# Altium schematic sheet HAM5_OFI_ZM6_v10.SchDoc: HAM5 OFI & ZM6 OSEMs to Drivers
size C; Engineer: L. Sanchez; Organization: LIGO Laboratory; Address1: California Institute of Technology; Address2: Massachusetts Institute of Technology; DocumentNumber: D1002740; Revision: v10; SheetNumber: 3; SheetTotal: 8
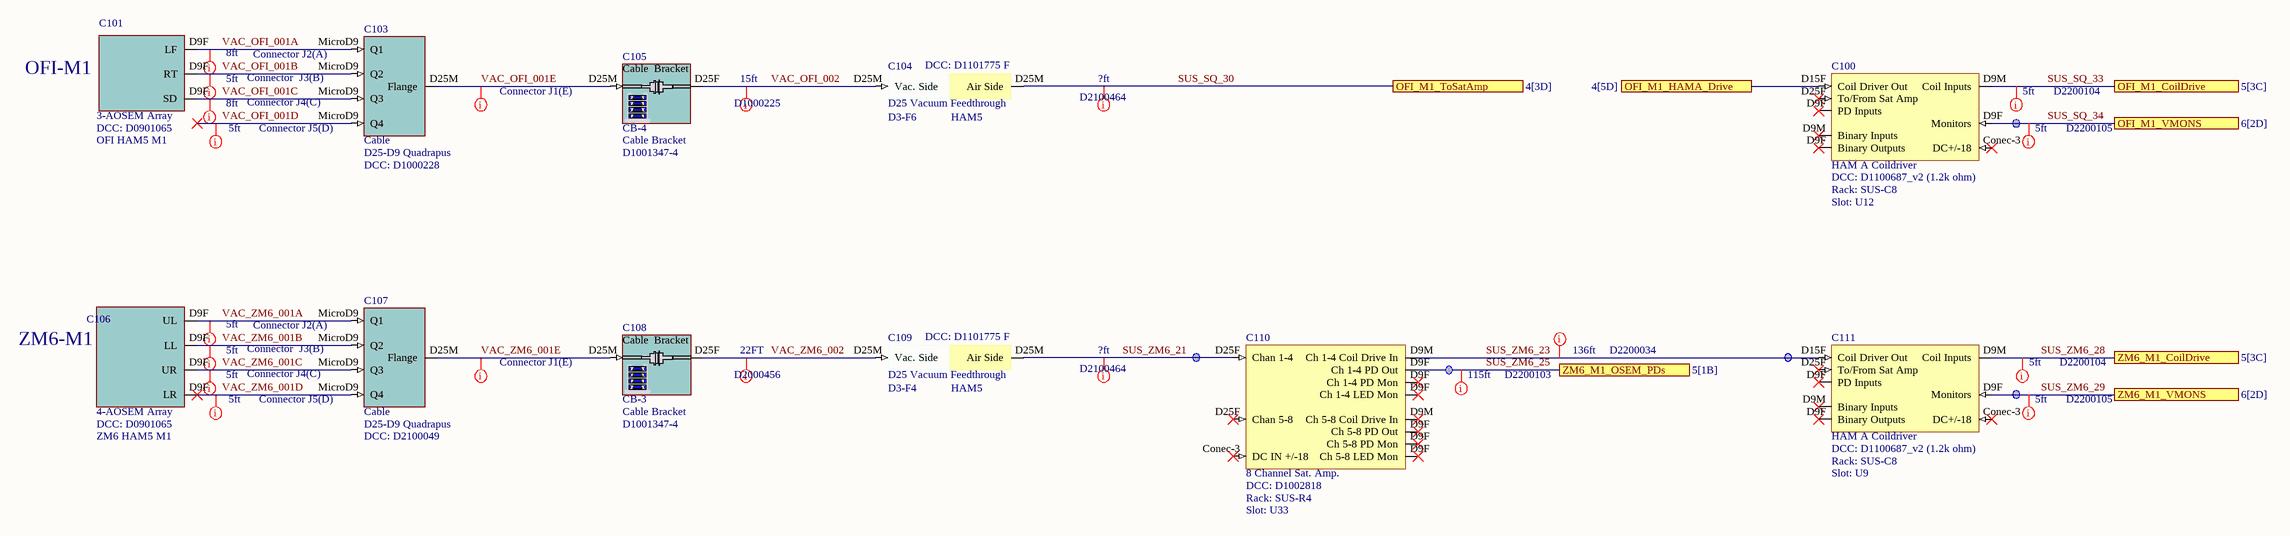
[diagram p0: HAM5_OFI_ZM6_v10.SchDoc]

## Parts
C100  HAM A Coildriver  DCC: D1100687_v2 (1.2k ohm)  Rack: SUS-C8  Slot: U12
C101  3-AOSEM Array  DCC: D0901065  Parameter: OFI HAM5 M1
C103  Cable  value D25-D9 Quadrapus  DCC: D1000228
C104  D25 Vacuum Feedthrough  DCC: D1101775 F  Feedthrough: D3-F6  Chamber: HAM5
C105  Slot: CB-4  DCC: D1001347-4  (hidden comment: Cable Bracket)
C106  4-AOSEM Array  DCC: D0901065  Parameter: ZM6 HAM5 M1
C107  Cable  value D25-D9 Quadrapus  DCC: D2100049
C108  Slot: CB-3  DCC: D1001347-4  (hidden comment: Cable Bracket)
C109  D25 Vacuum Feedthrough  DCC: D1101775 F  Feedthrough: D3-F4  Chamber: HAM5
C110  8 Channel Sat. Amp.  DCC: D1002818  Rack: SUS-R4  Slot: U33
C111  HAM A Coildriver  DCC: D1100687_v2 (1.2k ohm)  Rack: SUS-C8  Slot: U9

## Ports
OFI_M1_CoilDrive (see 5[3C]), OFI_M1_HAMA_Drive (see 4[5D]), OFI_M1_ToSatAmp (see 4[3D]), OFI_M1_VMONS (see 6[2D]), ZM6_M1_CoilDrive (see 5[3C]), ZM6_M1_OSEM_PDs (see 5[1B]), ZM6_M1_VMONS (see 6[2D])

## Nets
OFI_M1_HAMA_Drive: C100.D15F(Coil_Driver_Out) ; port OFI_M1_HAMA_Drive
SUS_SQ_30: C104.D25M(Air_Side) ; port OFI_M1_ToSatAmp
SUS_SQ_33: C100.D9M(Coil_Inputs) ; port OFI_M1_CoilDrive
SUS_SQ_34: C100.D9F(PD_Inputs) ; port OFI_M1_VMONS
SUS_ZM6_21: C109.D25M(Air_Side) C110.D25F(Chan_1-4)
SUS_ZM6_23: C110.D9M(Ch_1-4_Coil_Drive_In) C111.D15F(Coil_Driver_Out)
SUS_ZM6_25: C110.D9F(Ch_1-4_PD_Out) ; port ZM6_M1_OSEM_PDs
SUS_ZM6_28: C111.D9M(Coil_Inputs) ; port ZM6_M1_CoilDrive
SUS_ZM6_29: C111.D9F(PD_Inputs) ; port ZM6_M1_VMONS
VAC_OFI_001A: C101.D9F(LF) C103.MicroD9(Q1)
VAC_OFI_001B: C101.D9F(RT) C103.MicroD9(Q2)
VAC_OFI_001C: C101.D9F(SD) C103.MicroD9(Q3)
VAC_OFI_001D: C103.MicroD9(Q4)
VAC_OFI_001E: C103.D25M(Flange) C105.D25M
VAC_OFI_002: C104.D25M(Vac._Side) C105.D25F
VAC_ZM6_001A: C106.D9F(UL) C107.MicroD9(Q1)
VAC_ZM6_001B: C106.D9F(LL) C107.MicroD9(Q2)
VAC_ZM6_001C: C106.D9F(UR) C107.MicroD9(Q3)
VAC_ZM6_001D: C106.D9F(LR) C107.MicroD9(Q4)
VAC_ZM6_001E: C107.D25M(Flange) C108.D25M
VAC_ZM6_002: C108.D25F C109.D25M(Vac._Side)

Not connected (* = marked no-connect by the designer): C100 Conec-3(DC+/-18)* D25F(To/From_Sat_Amp)*; C110 Conec-3(DC_IN_+/-18)*; C111 Conec-3(DC+/-18)* D25F(To/From_Sat_Amp)*

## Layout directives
Length: ?ft; DCC: D2100464: SUS_SQ_30, SUS_ZM6_21
Length: 15ft; DCC: D1000225: VAC_OFI_002
Length: 5ft; DCC: Connector J5(D): VAC_OFI_001D, VAC_ZM6_001D
Length: 8ft; DCC: Connector J2(A): VAC_OFI_001A
Length: 5ft; DCC: Connector  J3(B): VAC_OFI_001B, VAC_ZM6_001B
Length: 8ft; DCC: Connector J4(C): VAC_OFI_001C
Length: 5ft; DCC: Connector J1(E): VAC_OFI_001E, VAC_ZM6_001E
Length: 22FT; DCC: D2000456: VAC_ZM6_002
Length: 5ft; DCC: Connector J2(A): VAC_ZM6_001A
Length: 5ft; DCC: Connector J4(C): VAC_ZM6_001C
Length: 136ft; DCC: D2200034: SUS_ZM6_23
Length: 115ft; DCC: D2200103: SUS_ZM6_25
Length: 5ft; DCC: D2200104: SUS_SQ_33, SUS_ZM6_28
Length: 5ft; DCC: D2200105: SUS_SQ_34, SUS_ZM6_29

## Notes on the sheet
- OFI-M1
- ZM6-M1

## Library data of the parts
C100 C111 = HAM A Coildriver: Serial: Sxxxxxxx; System: ISC
C101 = 3-AOSEM Array: Rack: SUS-R?; Serial: Sxxxxxxx; Slot: U?; System: SUS
C103 C107 = Flange: Rack: SUS-R?; Serial: Sxxxxxxx; Slot: U?; System: SUS
C104 C109 = VacFeedD25: Serial: Sxxxxxxx; System: ISC; Rack: R?; Slot: U?
C105 = Cable Bracket 4 1-4: Rack: SUS-R?; Serial: Sxxxxxxx; System: SUS
C106 = 4-BOSEM Array: Rack: SUS-R?; Serial: Sxxxxxxx; Slot: U?; System: SUS
C108 = Cable Bracket 3 1-4: Rack: SUS-R?; Serial: Sxxxxxxx; System: SUS
C110 = 8 Channel Sat. Amp.: Serial: Sxxxxxxx; System: ISC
